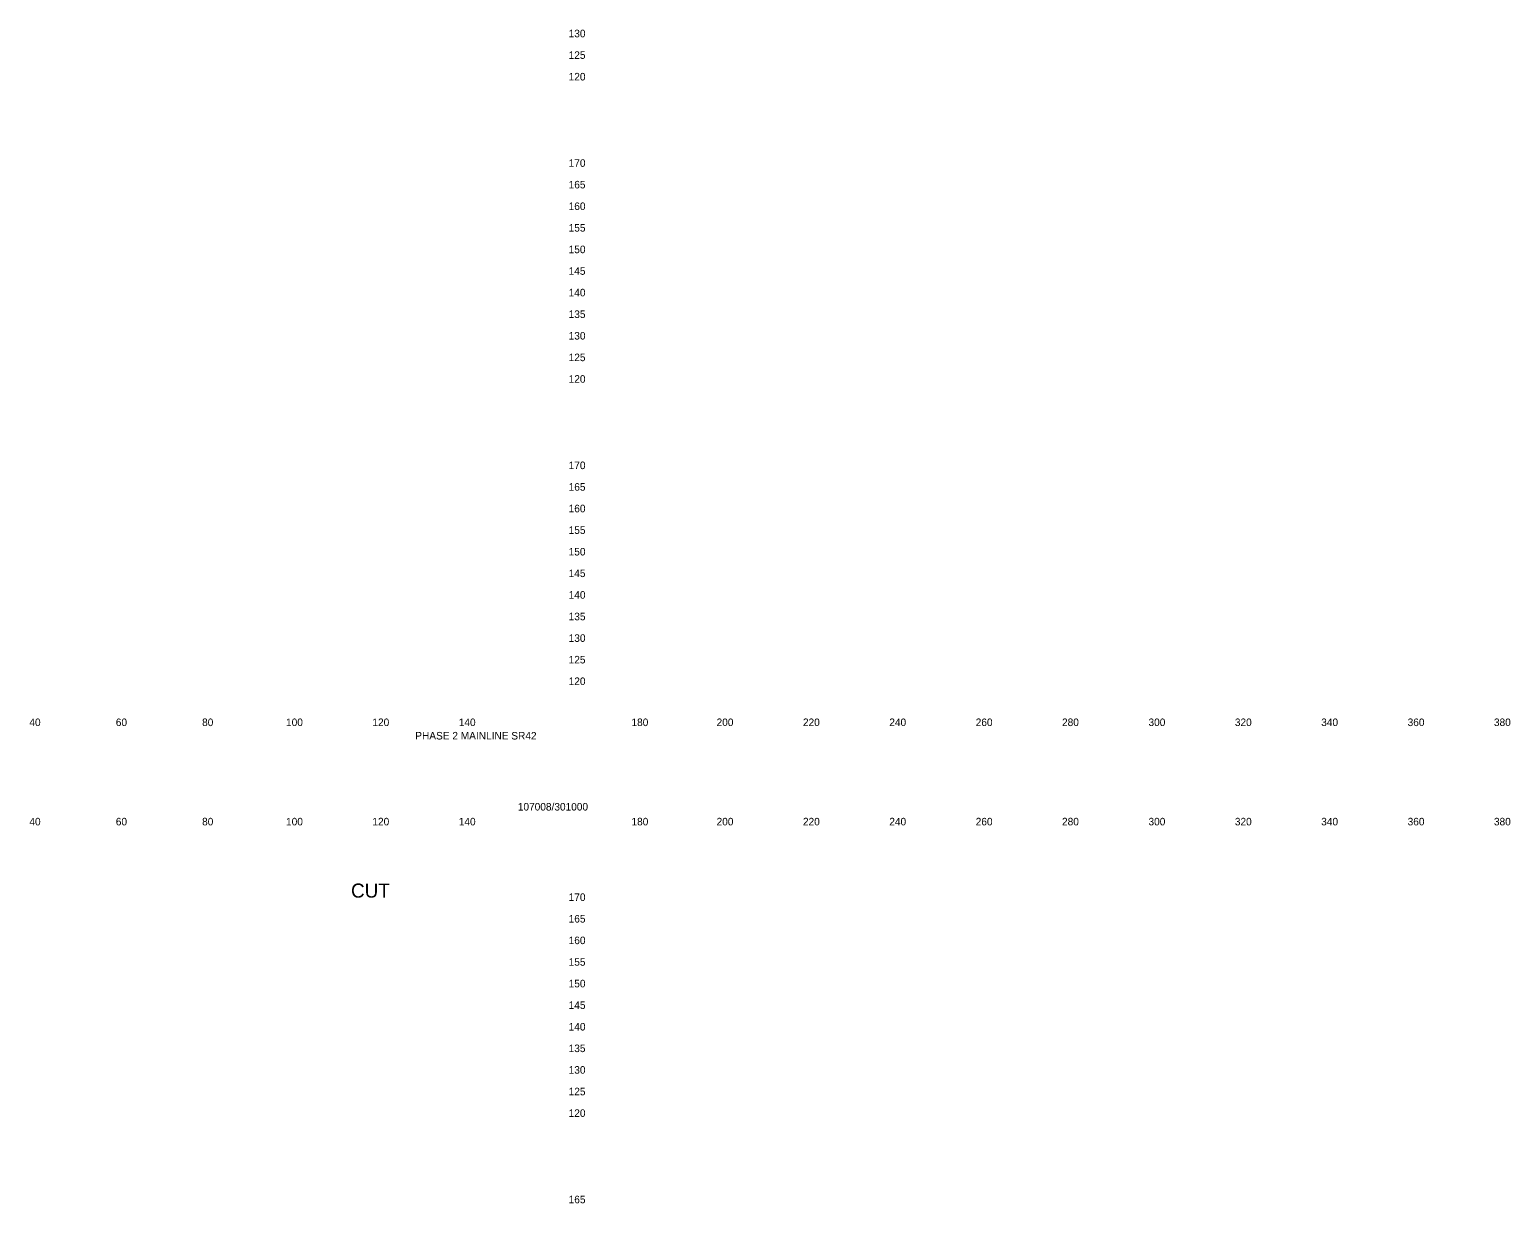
# Model space of a CAD drawing. Extents: x 21281 to 22024, y 6472 to 15208.
# Drawn here: x 21681.3 to 22024.2, y 7284.8 to 7556.6 of the extents above; entities that cross this region are included whole.
import ezdxf

# ---------------------------------------------------------------- set-up
doc = ezdxf.new("R2010")
doc.units = 0
doc.layers.add('XS_SHEET_LABELS_ELEVATION', color=7, linetype='Continuous')
doc.layers.add('XS_SHEET_LABELS_OFFSET', color=7, linetype='Continuous')

msp = doc.modelspace()

# ---------------------------------------------------------------- texts
at = {"layer": 'XS_SHEET_LABELS_ELEVATION'}
for s, p in [('  130  ', (21804.84, 7554.84)), ('  125  ', (21804.84, 7549.84)), ('  120  ', (21804.84, 7544.84)), ('  170  ', (21804.84, 7524.84)), ('  165  ', (21804.84, 7519.84)), ('  160  ', (21804.84, 7514.84)), ('  155  ', (21804.84, 7509.84)), ('  150  ', (21804.84, 7504.84)), ('  145  ', (21804.84, 7499.84)), ('  140  ', (21804.84, 7494.84)), ('  135  ', (21804.84, 7489.84)), ('  130  ', (21804.84, 7484.84)), ('  125  ', (21804.84, 7479.84)), ('  120  ', (21804.84, 7474.84)), ('  170  ', (21804.84, 7454.84)), ('  165  ', (21804.84, 7449.84)), ('  160  ', (21804.84, 7444.84)), ('  155  ', (21804.84, 7439.84)), ('  150  ', (21804.84, 7434.84)), ('  145  ', (21804.84, 7429.84)), ('  140  ', (21804.84, 7424.84)), ('  135  ', (21804.84, 7419.84)), ('  130  ', (21804.84, 7414.84)), ('  125  ', (21804.84, 7409.84)), ('  120  ', (21804.84, 7404.84)), ('  170  ', (21804.84, 7354.84)), ('  165  ', (21804.84, 7349.84)), ('  160  ', (21804.84, 7344.84)), ('  155  ', (21804.84, 7339.84)), ('  150  ', (21804.84, 7334.84)), ('  145  ', (21804.84, 7329.84)), ('  140  ', (21804.84, 7324.84)), ('  135  ', (21804.84, 7319.84)), ('  130  ', (21804.84, 7314.84)), ('  125  ', (21804.84, 7309.84)), ('  120  ', (21804.84, 7304.84)), ('  165  ', (21804.84, 7284.84))]:
    msp.add_text(s, height=1.75, dxfattribs=at).set_placement(p)
at = {"layer": 'XS_SHEET_LABELS_OFFSET'}
for s, height, p in [('  40  ', 1.75, (21679.95, 7395.34)), ('  60  ', 1.75, (21699.97, 7395.34)), ('  80  ', 1.75, (21719.95, 7395.34)), ('  100  ', 1.75, (21739.39, 7395.34)), ('  120  ', 1.75, (21759.39, 7395.34)), ('  140  ', 1.75, (21779.39, 7395.34)), ('  180  ', 1.75, (21819.39, 7395.34)), ('  200  ', 1.75, (21839.1, 7395.34)), ('  220  ', 1.75, (21859.1, 7395.34)), ('  240  ', 1.75, (21879.1, 7395.34)), ('  260  ', 1.75, (21899.11, 7395.34)), ('  280  ', 1.75, (21919.1, 7395.34)), ('  300  ', 1.75, (21939.13, 7395.34)), ('  320  ', 1.75, (21959.13, 7395.34)), ('  340  ', 1.75, (21979.13, 7395.34)), ('  360  ', 1.75, (21999.14, 7395.34)), ('  380  ', 1.75, (22019.13, 7395.34)), ('PHASE 2 MAINLINE SR42', 1.75, (21770.62, 7392.23)), ('107008/301000', 1.75, (21794.37, 7375.78)), ('  40  ', 1.75, (21679.95, 7372.34)), ('  60  ', 1.75, (21699.97, 7372.34)), ('  80  ', 1.75, (21719.95, 7372.34)), ('  100  ', 1.75, (21739.39, 7372.34)), ('  120  ', 1.75, (21759.39, 7372.34)), ('  140  ', 1.75, (21779.39, 7372.34)), ('  180  ', 1.75, (21819.39, 7372.34)), ('  200  ', 1.75, (21839.1, 7372.34)), ('  220  ', 1.75, (21859.1, 7372.34)), ('  240  ', 1.75, (21879.1, 7372.34)), ('  260  ', 1.75, (21899.11, 7372.34)), ('  280  ', 1.75, (21919.1, 7372.34)), ('  300  ', 1.75, (21939.13, 7372.34)), ('  320  ', 1.75, (21959.13, 7372.34)), ('  340  ', 1.75, (21979.13, 7372.34)), ('  360  ', 1.75, (21999.14, 7372.34)), ('  380  ', 1.75, (22019.13, 7372.34)), ('CUT', 3.273, (21755.74, 7355.61))]:
    msp.add_text(s, height=height, dxfattribs=at).set_placement(p)

doc.saveas('drawing.dxf')
